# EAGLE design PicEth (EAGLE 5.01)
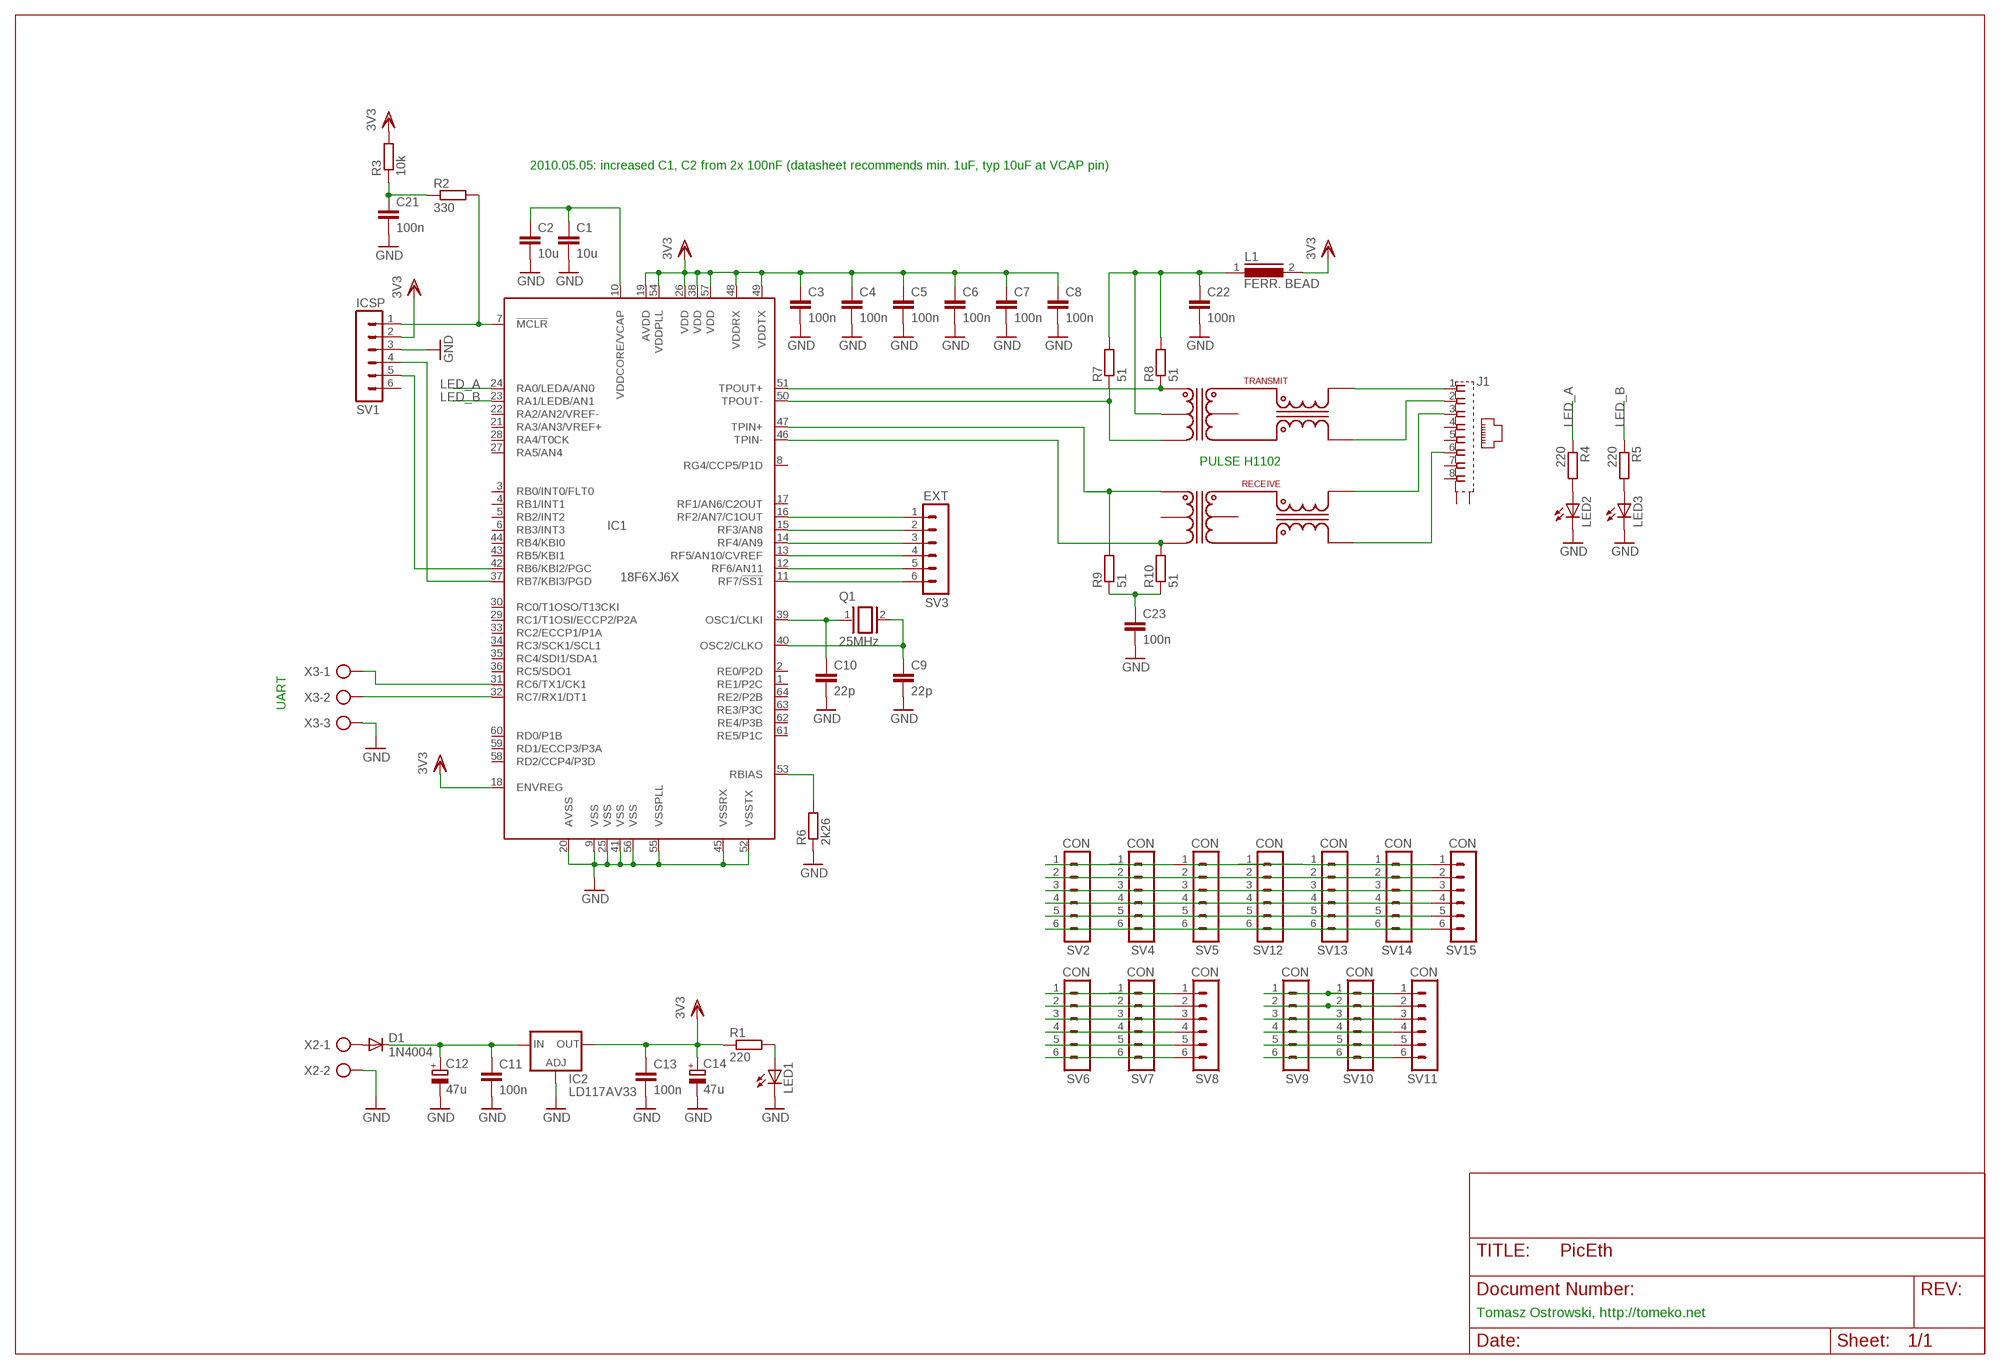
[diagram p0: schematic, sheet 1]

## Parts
C1  10u  C-0805  [C0805]
C2  10u  C-0805  [C0805]
C3  100n  C-0805  [C0805]
C4  100n  C-0805  [C0805]
C5  100n  C-0805  [C0805]
C6  100n  C-0805  [C0805]
C7  100n  C-0805  [C0805]
C8  100n  C-0805  [C0805]
C9  22p  C-0805  [C0805]
C10  22p  C-0805  [C0805]
C11  100n  C-0805  [C0805]
C12  47u  CPOL-EUE2.5-6  [E2,5-6]
C13  100n  C-0805  [C0805]
C14  47u  CPOL-EUE2.5-6  [E2,5-6]
C21  100n  C-0805  [C0805]
C22  100n  C-0805  [C0805]
C23  100n  C-0805  [C0805]
D1  1N4004  [DO41-10]
IC1  18F6XJ6X  [TQFP64-10X10]
IC2  LD117AV33  [TO220L1]
J1  555141-1  [555153-1]
L1  FERR. BEAD  MMICC7  [MMICC7]
LED1  LED5MM  [LED5MM]
LED2  LED5MM  [LED5MM]
LED3  LED5MM  [LED5MM]
Q1  25MHz  XTAL/S  [QS]
R1  220  R-EU_0207/10  [0207/10]
R2  330  R-EU_0207/10  [0207/10]
R3  10k  R-EU_0207/10  [0207/10]
R4  220  R-EU_0207/10  [0207/10]
R5  220  R-EU_0207/10  [0207/10]
R6  2k26  R-EU_0207/10  [0207/10]
R7  51  R-EU_0207/10  [0207/10]
R8  51  R-EU_0207/10  [0207/10]
R9  51  R-EU_0207/10  [0207/10]
R10  51  R-EU_0207/10  [0207/10]
SV1  ICSP  MA06-1  [MA06-1]
SV2  CON  MA06-1  [MA06-1]
SV3  EXT  MA06-1  [MA06-1]
SV4  CON  MA06-1  [MA06-1]
SV5  CON  MA06-1  [MA06-1]
SV6  CON  MA06-1  [MA06-1]
SV7  CON  MA06-1  [MA06-1]
SV8  CON  MA06-1  [MA06-1]
SV9  CON  MA06-1  [MA06-1]
SV10  CON  MA06-1  [MA06-1]
SV11  CON  MA06-1  [MA06-1]
SV12  CON  MA06-1  [MA06-1]
SV13  CON  MA06-1  [MA06-1]
SV14  CON  MA06-1  [MA06-1]
SV15  CON  MA06-1  [MA06-1]
U$1  H1102  [H11XX]
X2  AK500/2  [AK500/2]
X3  AK500/3  [AK500/3]

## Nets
GND: C1.2 C2.2 C3.2 C4.2 C5.2 C6.2 C7.2 C8.2 C9.2 C10.2 C11.2 C12.- C13.2 C14.- C21.2 C22.2 C23.2 IC1.9(VSS) IC1.20(AVSS) IC1.25(VSS) IC1.41(VSS) IC1.45(VSSRX) IC1.52(VSSTX) IC1.55(VSSPLL) IC1.56(VSS) IC2.1(ADJ) LED1.K(C) LED2.K(C) LED3.K(C) R6.1 SV1.3 X2.2 X3.3
LED_A: IC1.24(RA0/LEDA/AN0) R4.1
LED_B: IC1.23(RA1/LEDB/AN1) R5.1
N$1: J1.1 U$1.16
N$2: J1.2 U$1.14
N$3: IC1.7(!MCLR) R2.2 SV1.1
N$4: C21.1 R2.1 R3.1
N$5: C1.1 C2.1 IC1.10(VDDCORE/VCAP)
N$6: IC1.42(RB6/KBI2/PGC) SV1.5
N$7: IC1.37(RB7/KBI3/PGD) SV1.4
N$8: IC1.46(TPIN-) R10.2 U$1.8
N$9: J1.6 U$1.9
N$10: IC1.51(TPOUT+) R8.1 U$1.1
N$11: C22.1 L1.1 R7.2 R8.2 U$1.2
N$12: C10.1 IC1.39(OSC1/CLKI) Q1.1
N$13: C9.1 IC1.40(OSC2/CLKO) Q1.2
N$14: IC1.32(RC7/RX1/DT1) X3.2
N$15: D1.A X2.1
N$16: C11.1 C12.+ D1.C IC2.3(IN)
N$17: IC1.31(RC6/TX1/CK1) X3.1
N$18: LED1.A R1.2
N$19: J1.3 U$1.11
N$20: LED2.A R4.2
N$21: LED3.A R5.2
N$22: IC1.16(RF2/AN7/C1OUT) SV3.1
N$23: IC1.15(RF3/AN8) SV3.2
N$24: IC1.14(RF4/AN9) SV3.3
N$25: IC1.13(RF5/AN10/CVREF) SV3.4
N$26: IC1.12(RF6/AN11) SV3.5
N$27: IC1.50(TPOUT-) R7.1 U$1.3
N$28: IC1.47(TPIN+) R9.2 U$1.6
N$29: C23.1 R9.1 R10.1
N$30: IC1.11(RF7/!SS1) SV3.6
N$31: SV2.1 SV5.1
N$32: SV2.2 SV5.2 SV12.2 SV13.2 SV14.2 SV15.2
N$33: SV2.3 SV4.3 SV5.3 SV12.3 SV13.3 SV14.3 SV15.3
N$34: SV2.4 SV4.4 SV5.4 SV12.4 SV13.4 SV14.4 SV15.4
N$35: SV2.5 SV4.5 SV5.5 SV12.5 SV13.5 SV14.5 SV15.5
N$36: SV2.6 SV4.6 SV5.6 SV12.6 SV13.6 SV14.6 SV15.6
N$37: SV6.1 SV8.1
N$38: SV6.2 SV8.2
N$39: SV6.3 SV7.3 SV8.3
N$40: SV6.4 SV7.4 SV8.4
N$41: SV6.5 SV7.5 SV8.5
N$42: SV6.6 SV7.6 SV8.6
N$43: SV9.1 SV10.1 SV11.1
N$44: SV9.2 SV10.2 SV11.2
N$45: SV9.3 SV10.3 SV11.3
N$46: SV9.4 SV10.4 SV11.4
N$47: SV9.5 SV10.5 SV11.5
N$48: SV9.6 SV10.6 SV11.6
N$49: SV12.1 SV13.1 SV14.1 SV15.1
N$50: IC1.53(RBIAS) R6.2
VDD: C3.1 C4.1 C5.1 C6.1 C7.1 C8.1 C13.1 C14.+ IC1.18(ENVREG) IC1.19(AVDD) IC1.26(VDD) IC1.38(VDD) IC1.48(VDDRX) IC1.49(VDDTX) IC1.54(VDDPLL) IC1.57(VDD) IC2.2(OUT) L1.2 R1.1 R3.2 SV1.2 ; supply symbol labelled 3V3
Unconnected: IC1.1(RE1/P2C) IC1.2(RE0/P2D) IC1.3(RB0/INT0/FLT0) IC1.4(RB1/INT1) IC1.5(RB2/INT2) IC1.6(RB3/INT3) IC1.8(RG4/CCP5/P1D) IC1.17(RF1/AN6/C2OUT) IC1.21(RA3/AN3/VREF+) IC1.22(RA2/AN2/VREF-) IC1.27(RA5/AN4) IC1.28(RA4/T0CK) IC1.29(RC1/T1OSI/ECCP2/P2A) IC1.30(RC0/T1OSO/T13CKI) IC1.33(RC2/ECCP1/P1A) IC1.34(RC3/SCK1/SCL1) IC1.35(RC4/SDI1/SDA1) IC1.36(RC5/SDO1) IC1.43(RB5/KBI1) IC1.44(RB4/KBI0) IC1.58(RD2/CCP4/P3D) IC1.59(RD1/ECCP3/P3A) IC1.60(RD0/P1B) IC1.61(RE5/P1C) IC1.62(RE4/P3B) IC1.63(RE3/P3C) IC1.64(RE2/P2B) J1.4 J1.5 J1.7 J1.8 J1.G1(S1) J1.G2(S2) SV1.6 SV4.1 SV4.2 SV7.1 SV7.2 U$1.7 U$1.10 U$1.15

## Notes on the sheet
- 2010.05.05: increased C1, C2 from 2x 100nF (datasheet recommends min. 1uF, typ 10uF at VCAP pin)
- PULSE H1102
- UART
- Tomasz Ostrowski, http://tomeko.net

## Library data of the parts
C1-C11 C13 C21-C23 = quantum-sensor:C: Capacitor
C12 C14 = rcl:CPOL-EU: POLARIZED CAPACITOR, European symbol
D1 = diode:1N4004: DIODE
IC1 = microchip_enet:18F6XJ6X
IC2 = v-reg:LD117A?*: Low drop fixed and adjustable positive voltage regulators 1 A Source: http://www.st.com/stonline/products/literature/ds/7194/ld1117axx.pdf
J1 = con-amp:555141-1: AMP connector
L1 = inductors:MMICC7: INDUCTOR
LED1-LED3 = led:LED: LED
Q1 = special:XTAL/S: CRYSTAL
R1-R10 = rcl:R-EU_: RESISTOR, European symbol
SV1-SV15 = con-lstb:MA06-1: PIN HEADER
U$1 = trafo-pulse:H1102: PULSE SMT Ethernet transformer RX 1:1, TX 1:1, Central Tap
X2 = con-ptr500:AK500/2: CONNECTOR
X3 = con-ptr500:AK500/3: CONNECTOR

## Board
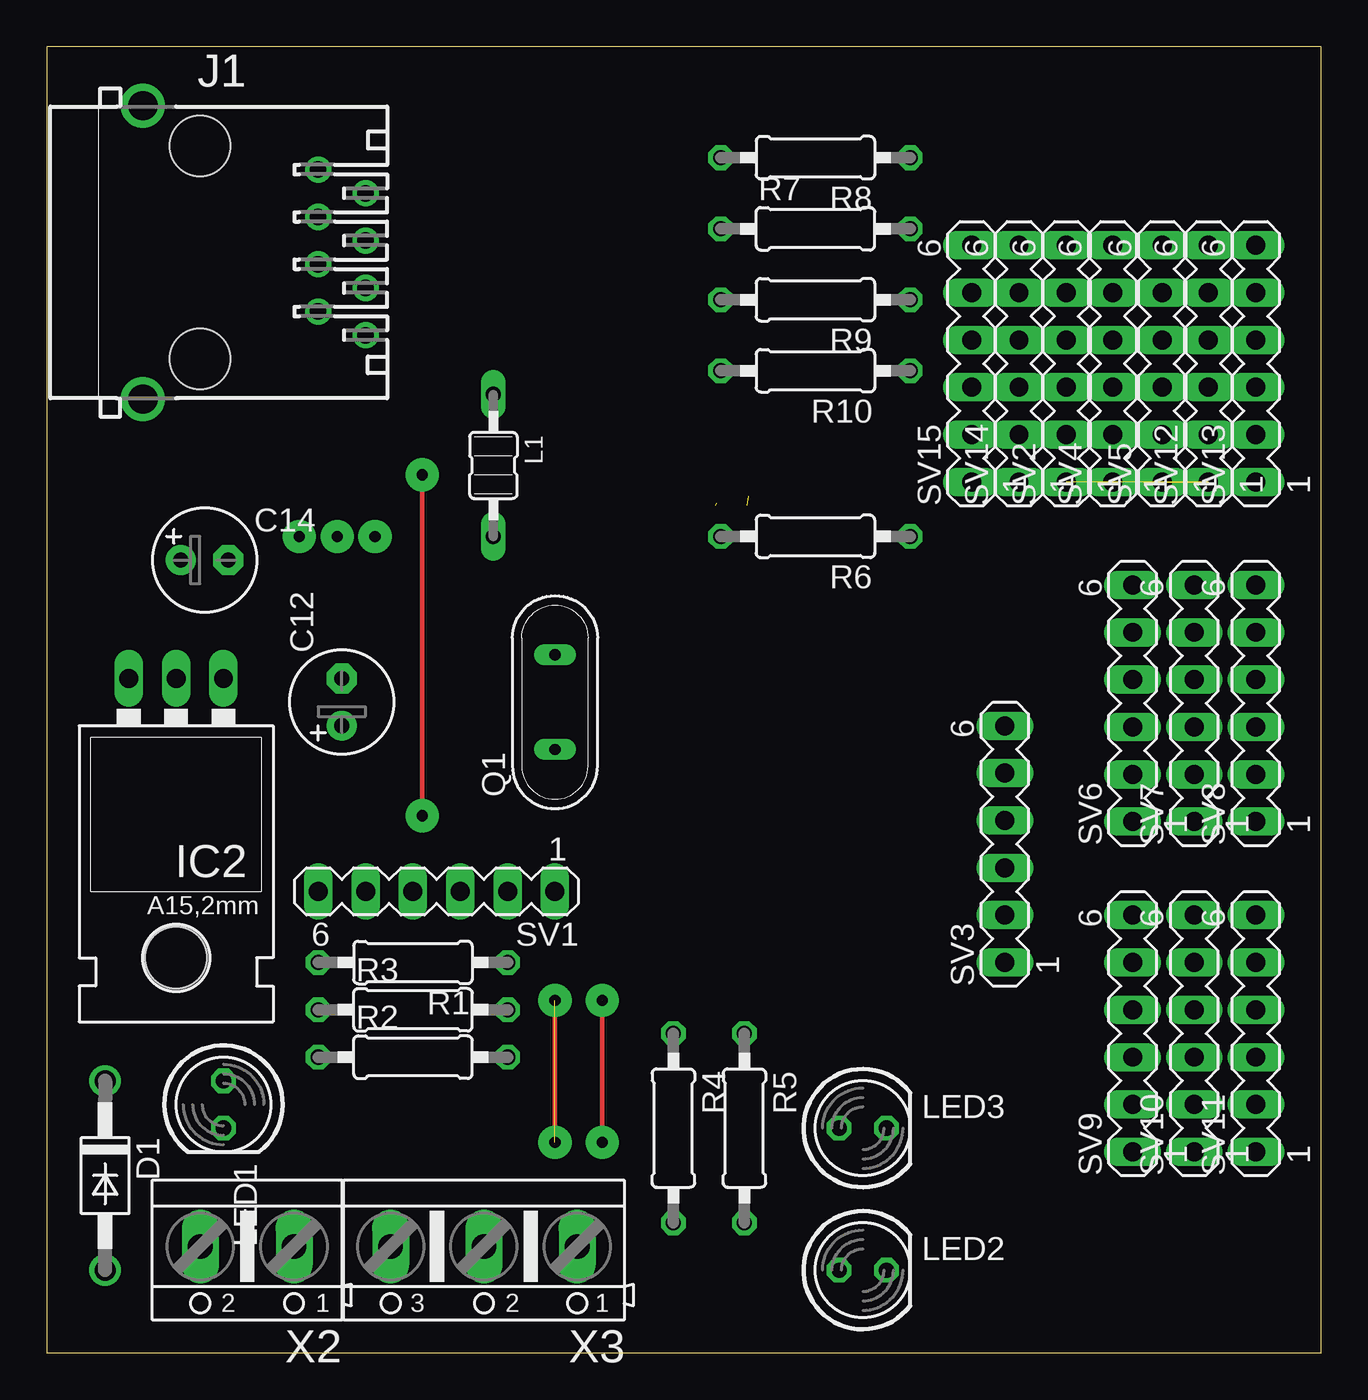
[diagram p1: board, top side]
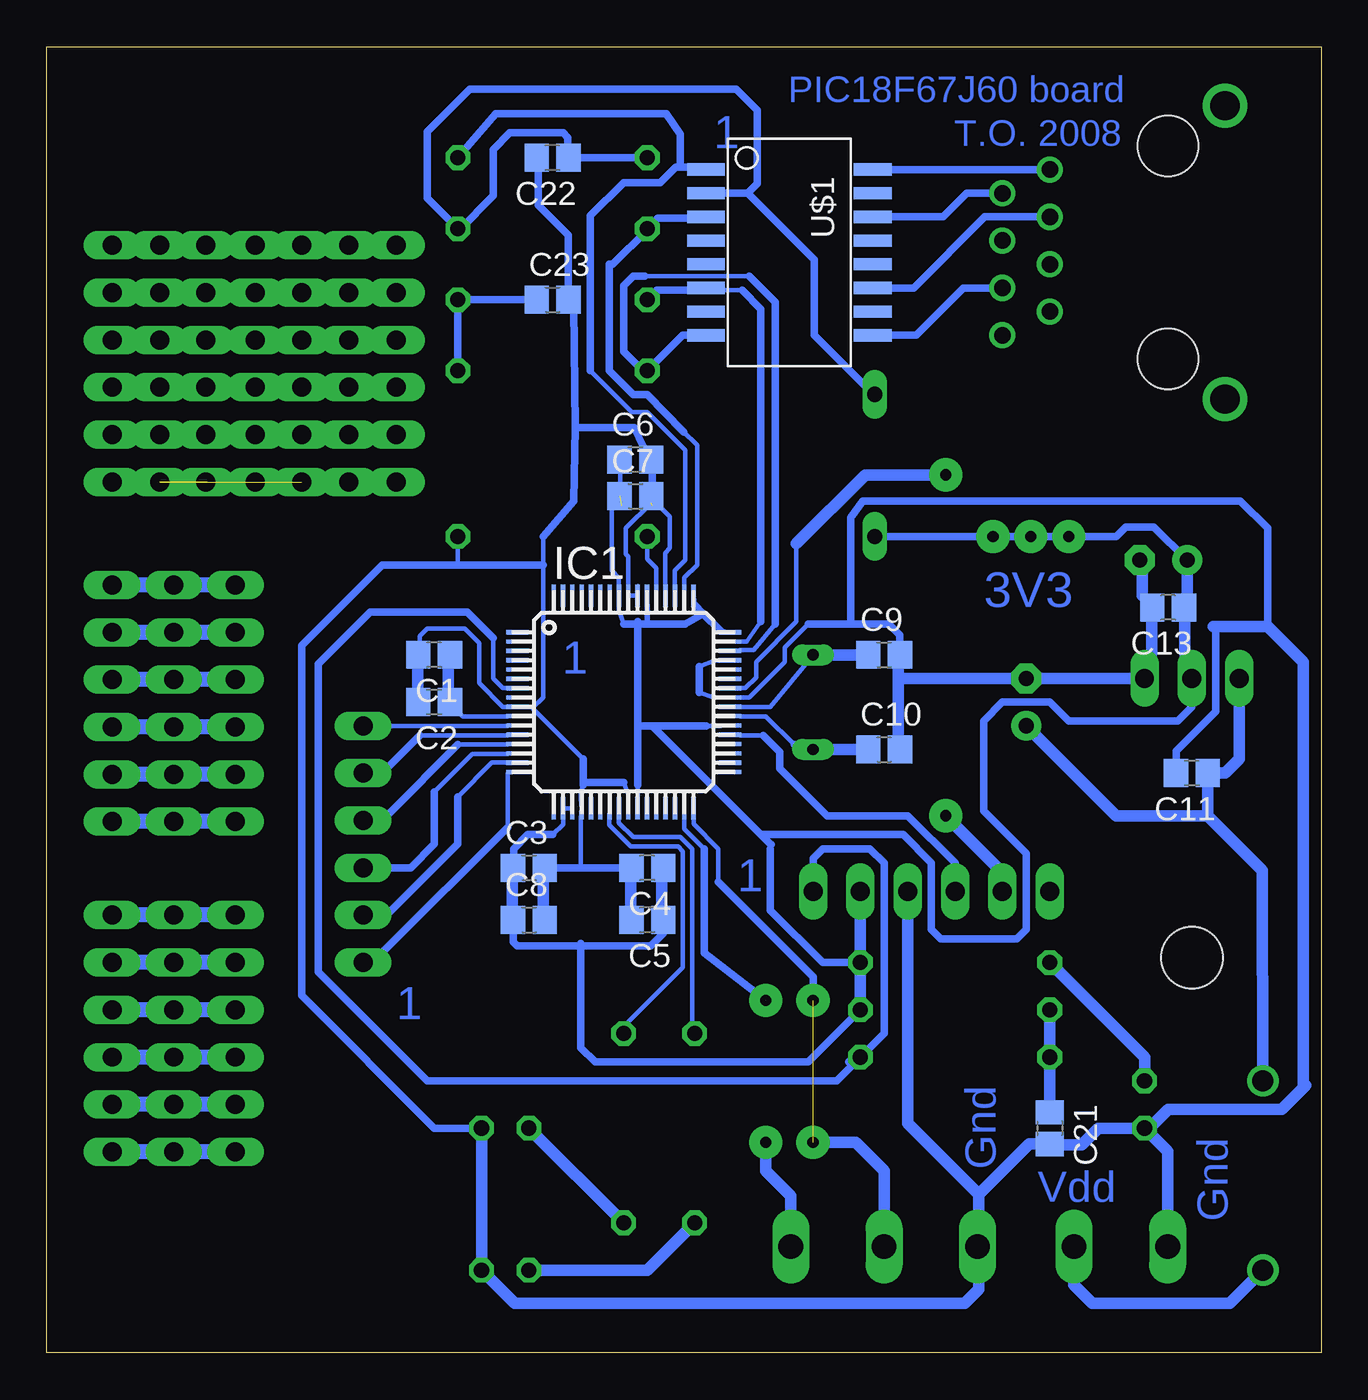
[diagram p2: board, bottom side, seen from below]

Size 68.38 x 70.09 mm. Coordinates in mm from the lower left corner, seen from the top.
Outline: 0,0 68.38,0 68.38,70.09 0,70.09 0,0
Copper layers (1*16): Top 0.035mm / dielectric 1.5mm / Bottom 0.035mm
Design rules "default *": minimum track width 10mil, minimum drill 24mil, track to track 7mil, track to pad 7mil, pad to pad 7mil, via to via 7mil, smd to smd 7mil, copper to edge 40mil, drill to drill 8mil, minimum pad ring 10mil, minimum via ring 8mil, stop-mask expansion 4mil, vias tented up to drill 0mil, thermal gap 10mil

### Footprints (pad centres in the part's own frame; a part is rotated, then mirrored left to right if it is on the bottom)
C0805 = smd 1.3 x 1.5: 1 -0.85,0; 2 0.85,0
E2,5-6 = drill 0.813 pad 1.6 round: + -1.27,0 | drill 0.813 pad 1.6 octagon: - 1.27,0
DO41-10 = drill 1.118 round: A 5.08,0; C -5.08,0
TQFP64-10X10 = smd 1.2 x 0.229: 1 -5.7,3.75; 2 -5.7,3.25; 3 -5.7,2.75; 4 -5.7,2.25; 5 -5.7,1.75; 6 -5.7,1.25; 7 -5.7,0.75; 8 -5.7,0.25; 9 -5.7,-0.25; 10 -5.7,-0.75; 11 -5.7,-1.25; 12 -5.7,-1.75; 13 -5.7,-2.25; 14 -5.7,-2.75; 15 -5.7,-3.25; 16 -5.7,-3.75; 33 5.7,-3.75; 34 5.7,-3.25; 35 5.7,-2.75; 36 5.7,-2.25; 37 5.7,-1.75; 38 5.7,-1.25; 39 5.7,-0.75; 40 5.7,-0.25; 41 5.7,0.25; 42 5.7,0.75; 43 5.7,1.25; 44 5.7,1.75; 45 5.7,2.25; 46 5.7,2.75; 47 5.7,3.25; 48 5.7,3.75 | smd 0.229 x 1.2: 17 -3.75,-5.7; 18 -3.25,-5.7; 19 -2.75,-5.7; 20 -2.25,-5.7; 21 -1.75,-5.7; 22 -1.25,-5.7; 23 -0.75,-5.7; 24 -0.25,-5.7; 25 0.25,-5.7; 26 0.75,-5.7; 27 1.25,-5.7; 28 1.75,-5.7; 29 2.25,-5.7; 30 2.75,-5.7; 31 3.25,-5.7; 32 3.75,-5.7; 49 3.75,5.7; 50 3.25,5.7; 51 2.75,5.7; 52 2.25,5.7; 53 1.75,5.7; 54 1.25,5.7; 55 0.75,5.7; 56 0.25,5.7; 57 -0.25,5.7; 58 -0.75,5.7; 59 -1.25,5.7; 60 -1.75,5.7; 61 -2.25,5.7; 62 -2.75,5.7; 63 -3.25,5.7; 64 -3.75,5.7
TO220L1 = drill 1.016 long: 1 -2.54,-3.81; 2 0,-3.81; 3 2.54,-3.81 | hole 3.302: 0,11.176
555153-1 = drill 0.889 round: 1 -4.445,6.35; 2 -3.175,8.89; 3 -1.905,6.35; 4 -0.635,8.89; 5 0.635,6.35; 6 1.905,8.89; 7 3.175,6.35; 8 4.445,8.89 | drill 1.575 pad 2.184 round: G1 -7.874,-3.048; G2 7.874,-3.048 | hole 3.251: -5.715,0; 5.715,0
MMICC7 = drill 0.813 long: 1 -3.81,0; 2 3.81,0
LED5MM = drill 0.813 octagon: A -1.27,0; K 1.27,0
QS = drill 0.61 long: 1 -2.54,0; 2 2.54,0
0207/10 = drill 0.813 octagon: 1 -5.08,0; 2 5.08,0
MA06-1 = drill 1.016 long: 1 -6.35,0; 2 -3.81,0; 3 -1.27,0; 4 1.27,0; 5 3.81,0; 6 6.35,0
H11XX = smd 0.66 x 2.032: 1 -4.445,-4.47; 2 -3.175,-4.47; 3 -1.905,-4.47; 4 -0.635,-4.47; 5 0.635,-4.47; 6 1.905,-4.47; 7 3.175,-4.47; 8 4.445,-4.47; 9 4.445,4.47; 10 3.175,4.47; 11 1.905,4.47; 12 0.635,4.47; 13 -0.635,4.47; 14 -1.905,4.47; 15 -3.175,4.47; 16 -4.445,4.47
AK500/2 = drill 1.321 long: 1 -2.515,0; 2 2.515,0
AK500/3 = drill 1.321 long: 1 -5.004,0; 2 0,0; 3 5.004,0

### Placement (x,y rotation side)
C1  47.59,37.46 180 bottom
C2  47.59,34.92 180 bottom
C3  42.51,26.03 0 bottom
C4  36.16,26.03 180 bottom
C5  36.16,23.24 180 bottom
C6  36.79,47.94 0 bottom
C7  36.79,45.97 0 bottom
C8  42.51,23.24 0 bottom
C9  23.46,37.46 0 bottom
C10  23.46,32.38 0 bottom
C11  6.95,31.11 180 bottom
C12  15.84,34.92 90 top
C13  8.22,40 180 bottom
C14  8.47,42.54 0 top
C21  14.57,12.06 270 bottom
C22  41.24,64.13 180 bottom
C23  41.24,56.51 0 bottom
D1  3.14,9.52 270 top
IC1  37.43,34.92 0 bottom
IC2  6.95,32.38 180 top
J1  8.22,59.05 270 top
L1  23.96,47.62 270 top
LED1  9.49,13.33 270 top
LED2  43.78,4.44 0 top
LED3  43.78,12.06 0 top
Q1  27.27,34.92 90 top
R1  19.65,20.95 180 top
R2  19.65,15.87 0 top
R3  19.65,18.41 0 top
R4  33.62,12.06 270 top
R5  37.43,12.06 270 top
R6  41.24,43.81 180 top
R7  41.24,60.32 0 top
R8  41.24,64.13 180 top
R9  41.24,56.51 180 top
R10  41.24,52.7 180 top
SV1  20.92,24.76 180 top
SV2  54.7,53.08 90 top
SV3  51.4,27.3 90 top
SV4  57.18,53.08 90 top
SV5  59.84,53.08 90 top
SV6  58.26,34.86 90 top
SV7  61.56,34.86 90 top
SV8  64.86,34.86 90 top
SV9  58.26,17.14 90 top
SV10  61.56,17.14 90 top
SV11  64.86,17.14 90 top
SV12  62.32,53.08 90 top
SV13  64.86,53.08 90 top
SV14  52.16,53.08 90 top
SV15  49.62,53.08 90 top
U$1  28.54,59.05 270 bottom
X2  10.76,5.71 180 top
X3  23.46,5.71 180 top

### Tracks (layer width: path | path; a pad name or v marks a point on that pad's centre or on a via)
GND  (1 unrouted)
  Bottom 0.254: 48.48,35.55 C2.2 | 48.48,36.83 C1.2 48.35,38.1 48.35,38.48 47.97,38.86 45.94,38.86 45.17,38.1 45.17,35.94 43.9,34.67 43.65,34.67 IC1.9 42.63,34.67 42.38,34.67 42.32,34.6 | 39.71,26.03 39.71,28.7 IC1.20 39.71,29.71 39.71,29.97 39.65,30.35 | 9.11,39.37 C13.2 9.61,40.64 | 22.7,33.02 C10.2 | C9.2 22.7,36.83 | 37.43,30.6 37.17,29.97 37.17,29.71 IC1.25 | 39.65,30.35 39.46,30.6 | 42.32,34.6 39.59,31.87 | 39.59,30.47 39.65,30.35 | IC1.52 35.2,40.95 35.2,42.92 34.95,43.18 34.95,44.89 35.97,45.91 35.94,45.93 C7.2 35.94,45.61 37.3,44.25 37.3,42.86 37.17,42.73 IC1.56 | 36.66,41.14 IC1.55 36.79,40.64 37.05,40.64 IC1.56 | 35.9,45.46 C6.2 | 41.74,43.81 41.74,42.29 41.74,35.17 42.32,34.6 | 41.74,23.87 C8.2 | C3.2 41.74,25.39 | 33.36,35.43 32.6,35.17 IC1.41 31.2,35.17 30.7,35.17 28.79,37.08 28.79,37.84 27.52,39.11 | IC1.45 31.75,37.14 32.54,37.14 33.36,36.83 | 37.05,23.87 C5.2 | C4.2 37.05,25.39 | IC1.56 37.17,40.57 | R6.1 46.32,42.35 46.38,42.29
  Bottom 0.406: C4.2 39.71,26.03 C3.2 | 39.46,30.6 37.43,30.6 | 39.59,31.87 39.59,30.47 | 33.36,35.43 33.36,36.83 | 25.23,39.11 27.52,39.11 | 25.23,39.11 25.23,44.83 24.6,45.72 4.34,45.72 2.88,44.25 2.88,38.98 | C11.2 7.8,32.29 5.68,34.41 5.68,38.98 | C9.2 22.61,38.52 23.2,39.11 25.23,39.11 | LED3.K 47.59,12.06 54.7,19.17 54.7,37.97 50.38,42.29 46.38,42.29 41.74,42.29 | 40.03,49.65 40.09,45.72 41.74,43.81 | 35.9,45.46 35.9,47.62 36.86,49.65 40.03,49.65 | C22.2 42,64.13 42,61.59 40.39,59.98 C23.2 40.48,56.51 arc90 40.09,56.13 40.03,49.65
  Bottom 0.61: 48.48,36.83 48.48,35.55 | 9.11,39.37 9.11,37.59 IC2.1 C12.- 22.7,36.19 | 22.7,36.83 22.7,36.19 | 22.7,36.19 22.7,33.02 | LED3.K LED2.K 43.27,2.66 19.14,2.66 18.38,3.42 18.38,5.71 | 41.74,25.39 41.74,23.87 | 9.61,40.64 9.61,41.78 C14.- | 37.05,25.39 37.05,23.87 | 18.38,8.5 15.67,11.21 C21.2 14.57,11.04 14.44,11.17 12.85,11.17 11.96,12.06 LED1.K | 18.38,5.71 X3.3 | 18.38,8.5 18.38,5.71 | X2.2 8.24,10.82 LED1.K | LED1.K 9.23,12.06 8.22,13.08 2.12,13.08 0.85,14.35 0.98,14.35 0.98,37.08 2.88,38.98 5.68,38.98 5.8,38.98 | SV1.3 22.19,12.31 18.38,8.5
LED_A
  Bottom 0.254: IC1.24 37.68,28.7 37.68,28.44 36.92,27.68 34.38,27.68 33.74,27.05 33.74,17.77 R4.1
LED_B
  Bottom 0.254: IC1.23 38.19,28.7 38.19,28.32 37.05,27.17 34.51,27.17 34.25,26.92 34.25,20.7 37.17,17.77 R5.1
N$1
  Bottom 0.406: U$1.16 J1.1
N$2
  Bottom 0.406: U$1.14 20.28,60.96 19.01,62.23 J1.2
N$3
  Bottom 0.254: IC1.7 43.65,35.68 43.9,35.68 44.41,36.19 44.41,38.35
  Bottom 0.406: 25.36,15.62 R2.2 | 44.41,38.35 45.81,39.75 51.02,39.75 53.81,36.95 53.81,20.44 47.97,14.6 26,14.6 R2.2 | R2.2 23.46,17.14 23.46,26.28 24.22,27.05 26.76,27.05 27.27,26.54 SV1.1
N$4
  Bottom 0.61: C21.1 R2.1 R3.1
N$5
  Bottom 0.254: IC1.10 43.65,34.16 46.06,34.16 46.19,34.29 C2.1 46.82,35.55 | 46.82,36.83 C1.1
  Bottom 0.61: 46.82,35.55 46.82,36.83
N$6  (via drill 0.6 pad 1.78)
  Top 0.254: v20.16,28.82 v20.16,47.11
  Bottom 0.254: IC1.42 30.9,35.67 30.31,36.25 30.31,37.08 28.16,39.24 28.16,43.43
  Bottom 0.61: 28.16,43.43 24.47,47.11 v20.16,47.11 | SV1.5 17.11,25.78 v20.16,28.82
  other vias: 29.81,18.92 27.27,18.92 29.81,11.3 27.27,11.3
N$7
  Bottom 0.254: 29.93,33.14 31.2,33.14 IC1.37
  Bottom 0.406: 29.93,33.14 29.05,32.25 29.05,31.36 26.5,28.82 22.19,28.82 19.65,26.28 SV1.4
N$8
  Bottom 0.254: 29.3,39.11 30.44,37.71 31.2,37.71 IC1.46 | 30.7,57.78 36.28,57.78
  Bottom 0.406: 29.3,39.11 29.3,56.38 30.7,57.78 | 36.28,57.78 36.92,57.78 37.43,57.27 37.43,53.72 36.41,52.7 R10.2 34.25,54.61 U$1.8
N$9
  Bottom 0.406: U$1.9 21.74,54.61 19.2,57.15 J1.6
N$10
  Bottom 0.254: U$1.1 33.24,63.5 33.36,63.37 33.62,63.62 | 39.2,52.7 36.98,50.48 36.16,50.48 34.76,49.08 | 34.76,49.08 34.7,49.02 | IC1.51 34.7,40.64 34.7,41.97 34.12,42.54 34.12,48.45 34.76,49.08
  Bottom 0.406: 34.38,63.62 34.63,63.62 35.46,62.8 37.43,62.8 39.2,61.02 39.2,52.7 | 33.62,63.62 34.38,63.62 | R8.1 44.28,66.48 35.14,66.48 34.38,65.4 34.38,63.62
N$11
  Bottom 0.406: C22.1 R8.2 40.41,64.13 40.41,65.21 40.67,65.46 43.52,65.46 44.41,64.57 44.41,62.1 46.25,60.26 R7.2 47.97,61.97 47.97,65.53 45.68,67.81 31.39,67.81 30.25,66.67 30.25,62.73 30.76,62.23 | 30.76,62.23 27.2,58.67 27.2,54.61 23.96,51.37 | 23.96,51.37 23.9,51.3 | 23.96,51.37 L1.1 | 30.76,62.23 U$1.2
N$12
  Bottom 0.254: 28.28,32.63 29.81,34.16 31.2,34.16 IC1.39
  Bottom 0.406: Q1.1 28.28,32.63
  Bottom 0.61: C10.1 Q1.1
N$13
  Bottom 0.254: Q1.2 29.55,34.67 31.2,34.67 IC1.40
  Bottom 0.61: C9.1 Q1.2
N$14  (via drill 0.6 pad 1.78)  (2 unrouted)
  Top 0.254: v27.27,11.3 v27.27,18.92
  Bottom 0.254: IC1.32 33.68,28.38 32.35,27.05 32.35,25.27
  Bottom 0.406: 32.35,25.27 27.27,20.19 v27.27,18.92
  Bottom 0.61: X3.2 23.46,9.77 24.98,11.3 v27.27,11.3
  other vias: 17.62,43.81 15.58,43.81 13.55,43.81
N$15
  Bottom 0.61: X2.1 13.27,3.65 12.28,2.66 4.92,2.66 D1.A
N$16
  Bottom 0.61: IC2.3 4.41,31.87 5.17,31.11 C11.1 6.1,28.82 | 6.1,28.82 3.18,25.88 D1.C | C12.+ 11.01,28.82 6.1,28.82
N$17  (via drill 0.6 pad 1.78)  (1 unrouted)
  Top 0.254: v29.81,11.3 29.81,18.92
  Bottom 0.254: IC1.31 34.18,28.11 33.11,27.05
  Bottom 0.406: 33.11,27.05 33.11,21.46 29.81,18.92
  Bottom 0.61: X3.1 28.46,8.43 29.81,9.77 v29.81,11.3
N$18
  Bottom 0.61: R1.2 9.49,15.87 LED1.A
N$19
  Bottom 0.406: U$1.11 21.87,57.15 18.06,60.96 J1.3
N$20
  Bottom 0.61: R4.2 36.16,4.44 LED2.A
N$21
  Bottom 0.61: R5.2 LED3.A
N$22
  Bottom 0.254: 43.65,28.19 43.65,31.11 IC1.16
  Bottom 0.406: 43.65,28.19 50.25,21.58 SV3.1
N$23
  Bottom 0.254: IC1.15 44.49,31.67 46.32,29.84
  Bottom 0.406: 46.32,29.84 46.32,27.3 50.13,23.49 SV3.2
N$24
  Bottom 0.254: IC1.14 43.65,32.13 45.55,32.13 47.59,30.09
  Bottom 0.406: 47.59,30.09 47.59,27.3 48.86,26.03 SV3.3
N$25
  Bottom 0.254: 46.32,32.63 43.65,32.63 IC1.13
  Bottom 0.406: 46.32,32.63 50,28.95 SV3.4
N$26
  Bottom 0.254: 48.35,33.14 43.65,33.14 IC1.12
  Bottom 0.406: 48.35,33.14 50,31.49 SV3.5
N$27
  Bottom 0.254: U$1.3 33.01,60.93 33.05,60.89 33.11,60.83 33.24,60.96 | IC1.50 34.18,41.6 33.49,42.29 33.49,48.7 34.25,49.46
  Bottom 0.406: 34.19,49.4 34.25,49.46 36.16,51.43 36.92,51.43 38.19,52.7 38.19,58.41 38,58.41 36.16,60.26 R7.1 35.59,60.89 33.05,60.89 33.05,60.92 U$1.3
N$28
  Bottom 0.254: U$1.6 33.73,56.96 | IC1.47 30.81,38.17 30.06,39.24 | U$1.6 33.01,57.12 33.11,57.02 31.08,57.02 | U$1.6 33.13,57.02
  Bottom 0.406: 30.06,39.24 30.06,56 31.08,57.02 | 33.13,57.02 35.65,57.02 R9.2
N$29
  Bottom 0.406: C23.1 R9.1 R10.1
N$30
  Bottom 0.254: IC1.11 43.65,33.65 SV3.6
N$31  (1 unrouted)
  Bottom 0.813: SV5.1 62.32,46.73
N$32
  Bottom 0.813: SV14.2 SV2.2 SV5.2 SV12.2 SV13.2
  Bottom 1.016: SV15.2 SV14.2
N$33
  Bottom 0.813: SV14.3 SV2.3 SV4.3 | SV4.3 57.24,51.81 | SV4.3 SV5.3 SV12.3 SV13.3
  Bottom 1.016: SV15.3 SV14.3
N$34
  Bottom 0.813: SV14.4 SV2.4 SV4.4 | SV4.4 57.24,54.35 | SV4.4 SV5.4 SV12.4 SV13.4
  Bottom 1.016: SV15.4 SV14.4
N$35
  Bottom 0.813: SV14.5 SV2.5 SV4.5 | SV4.5 57.24,56.89 | SV4.5 SV5.5 SV12.5 SV13.5
  Bottom 1.016: SV14.5 52.09,56.83 52.03,56.89 SV15.5
N$36
  Bottom 0.813: 52.29,59.43 SV2.6 SV4.6 | SV4.6 57.24,59.43 | SV4.6 SV5.6 SV12.6 SV13.6
  Bottom 1.016: SV14.6 52.29,59.43 SV15.6
N$37
  Bottom 0.813: 65.11,28.51 SV8.1 SV6.1
N$38
  Bottom 0.813: 65.11,31.05 SV8.2 SV6.2
N$39
  Bottom 0.813: SV6.3 61.3,33.59 | 61.3,33.59 SV7.3 | 61.3,33.59 SV8.3
N$40
  Bottom 0.813: SV6.4 61.3,36.13 | 61.3,36.13 SV7.4 | 61.3,36.13 SV8.4
N$41
  Bottom 0.813: SV6.5 SV7.5 SV8.5
N$42
  Bottom 0.813: SV6.6 SV7.6 SV8.6
N$43
  Bottom 0.813: SV9.1 SV10.1 SV11.1 65.37,10.79
N$44
  Bottom 0.813: SV9.2 SV10.2 SV11.2 65.37,13.33
N$45
  Bottom 0.813: SV9.3 SV10.3 SV11.3 65.37,15.87
N$46
  Bottom 0.813: SV9.4 SV10.4 SV11.4 65.37,18.41
N$47
  Bottom 0.813: SV9.5 SV10.5 SV11.5 65.37,20.95
N$48
  Bottom 0.813: SV9.6 SV10.6 SV11.6 65.37,23.49
N$49  (1 unrouted)
  Bottom 0.813: SV14.1 59.78,46.73 | SV12.1 SV13.1
  Bottom 1.016: SV15.1 SV14.1 52.22,46.67
N$50
  Bottom 0.254: IC1.53 35.68,42.12 36.16,42.6 R6.2
VDD  (1 unrouted)
  Bottom 0.254: IC1.19 40.22,29.2 40.6,29.2 IC1.18 40.68,28.37 41.24,27.81 | 7.33,39.37 C13.1 7.2,40.64 | 37.55,45.46 C6.1 | C8.1 43.4,23.87 | 43.4,25.39 C3.1 43.27,26.03 43.33,26.09 | 32.22,38.73 IC1.48 | 33.62,40.13 IC1.49 | 36.16,40.13 IC1.54 | 33.24,39.62 33.17,39.68 | 37.43,39.11 37.68,39.87 37.68,40.13 IC1.57 37.68,41.58 38.06,41.97 38.06,45.46 37.62,45.91 37.64,45.93 C7.1 | 36.16,39.11 36.03,39.11 | 36.66,30.47 36.66,29.71 IC1.26 | 32.98,33.65 32.22,33.65 IC1.38 | C5.1 35.39,23.87 | 35.39,25.39 C4.1 | 29.5,27.29 29.55,27.05
  Bottom 0.305: 36.16,39.11 36.16,40.13
  Bottom 0.406: 33.62,40.13 33.17,39.68 32.22,38.73 | 33.24,39.62 34.12,39.11 36.16,39.11 36.66,39.11 | 36.66,39.11 37.43,39.11 | 29.55,27.05 29.55,23.74 26.76,20.95 R1.1 | C8.1 43.36,22.05 43.14,21.84 39.71,21.84 | 41.24,27.81 42.57,27.81 43.33,27.05 43.33,26.09 | L1.2 11.01,43.81 10.5,44.32 8.98,44.32 C14.+ | 36.66,39.11 36.66,39.24 | 36.66,33.65 36.66,39.11 | 36.66,33.65 32.98,33.65 | 29.5,27.29 29.54,27.29 30.06,27.81 | 36.66,33.65 35.9,33.65 30.06,27.81 | 36.66,33.65 36.66,30.47 | R3.2 27.52,15.62 38.95,15.62 39.71,16.38 39.71,21.71 | 39.71,21.84 39.71,21.97 | 39.71,21.71 39.71,21.84 | C5.1 35.31,22.5 35.97,21.84 39.59,21.84 39.71,21.71 | IC2.2 6.95,34.67 7.71,33.9 13.55,33.9 14.57,34.92 17.11,34.92 18.12,33.9 18.12,29.08 15.84,26.79 15.84,22.73 16.34,22.22 20.41,22.22 20.92,22.73 20.92,26.28 22.44,27.81 30.06,27.81
  Bottom 0.61: 7.33,39.37 7.33,37.59 IC2.2 | R3.2 R1.1 SV1.2 | 43.4,23.87 43.4,25.39 | 7.2,40.64 C14.+ | 35.39,23.87 35.39,25.39

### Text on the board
Bottom: PIC18F67J60 board | T.O. 2008 | 1 | 3V3 | 1 | 1 | 1 | Gnd | Gnd | Vdd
